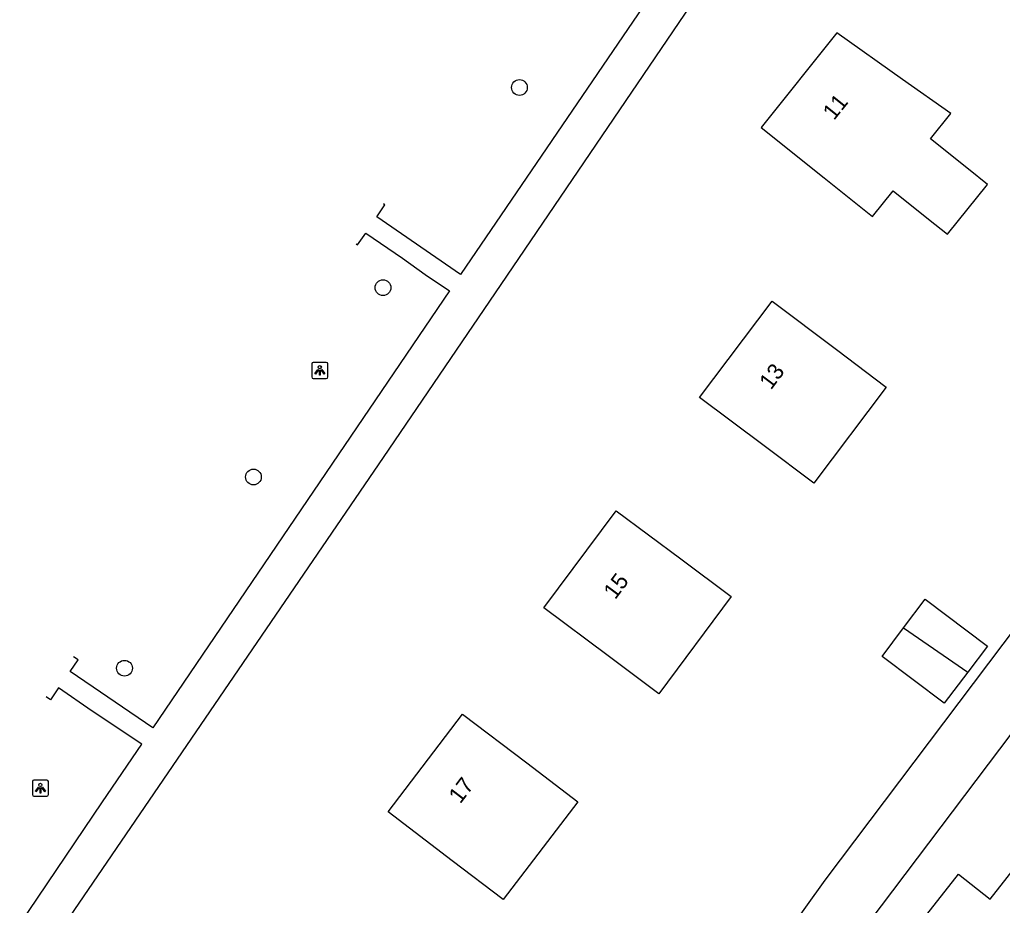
# Model space of a CAD drawing. Extents: x 158797 to 159887, y 384318 to 385255.
# Drawn here: x 159089 to 159149.9, y 385000.3 to 385055.3 of the extents above; entities that cross this region are included whole.
import ezdxf

# ---------------------------------------------------------------- set-up
doc = ezdxf.new("R2010")
doc.units = 0
for name, color, linetype in [('IMGEO_Boom', 7, 'Continuous'), ('IMGEO_Lichtpunt', 7, 'Continuous'), ('IMGEO_Pand', 7, 'Continuous'), ('IMGEO_Pand_nummerreeks', 7, 'Continuous'), ('IMGEO_Parkeervlak_open', 7, 'Continuous'), ('IMGEO_Rijbaan_lokaal_open', 7, 'Continuous'), ('IMGEO_Voetpad_open', 7, 'Continuous')]:
    doc.layers.add(name, color=color, linetype=linetype)

msp = doc.modelspace()

# ---------------------------------------------------------------- linework, layer by layer
at = {"layer": 'IMGEO_Boom'}
for centre in [(159119.974, 385051.109), (159111.509, 385038.687), (159103.468, 385026.934), (159095.468, 385015.062)]:
    msp.add_circle(centre, 0.489, dxfattribs=at)
at = {"layer": 'IMGEO_Lichtpunt'}
for p, q in [((159107.087, 385033.95), (159107.087, 385033.143)), ((159107.087, 385033.95), (159107.087, 385033.143)), ((159107.989, 385034.045), (159107.181, 385034.045)), ((159107.989, 385034.045), (159107.181, 385034.045)), ((159108.083, 385033.143), (159108.083, 385033.95)), ((159108.083, 385033.143), (159108.083, 385033.95)), ((159107.181, 385033.049), (159107.989, 385033.049)), ((159107.181, 385033.049), (159107.989, 385033.049)), ((159089.75, 385008.021), (159089.75, 385007.214)), ((159089.75, 385008.021), (159089.75, 385007.214)), ((159090.652, 385008.116), (159089.844, 385008.116)), ((159090.652, 385008.116), (159089.844, 385008.116)), ((159090.746, 385007.214), (159090.746, 385008.021)), ((159090.746, 385007.214), (159090.746, 385008.021)), ((159089.844, 385007.12), (159090.652, 385007.12)), ((159089.844, 385007.12), (159090.652, 385007.12))]:
    msp.add_line(p, q, dxfattribs=at)
for points in [[(159107.461, 385033.614), (159107.5, 385033.586), (159107.312, 385033.324), (159107.274, 385033.351), (159107.461, 385033.614)], [(159107.673, 385033.586), (159107.711, 385033.613), (159107.898, 385033.351), (159107.859, 385033.323), (159107.673, 385033.586)], [(159107.563, 385033.566), (159107.61, 385033.566), (159107.61, 385033.244), (159107.563, 385033.244), (159107.563, 385033.566)], [(159090.124, 385007.685), (159090.163, 385007.657), (159089.975, 385007.395), (159089.937, 385007.422), (159090.124, 385007.685)], [(159090.226, 385007.637), (159090.273, 385007.637), (159090.273, 385007.315), (159090.226, 385007.315), (159090.226, 385007.637)], [(159090.336, 385007.657), (159090.374, 385007.684), (159090.561, 385007.422), (159090.522, 385007.394), (159090.336, 385007.657)]]:
    msp.add_lwpolyline(points, dxfattribs=at)
for centre in [(159107.586, 385033.748), (159090.249, 385007.819)]:
    msp.add_circle(centre, 0.0994, dxfattribs=at)
for centre, start, end in [((159107.181, 385033.95), 90, 180), ((159107.181, 385033.95), 90, 180), ((159107.989, 385033.95), 0, 90), ((159107.989, 385033.95), 0, 90), ((159107.181, 385033.143), 180, 270), ((159107.181, 385033.143), 180, 270), ((159107.989, 385033.143), 270, 0), ((159107.989, 385033.143), 270, 360), ((159089.844, 385008.021), 90, 180), ((159089.844, 385008.021), 90, 180), ((159090.652, 385008.021), 0, 90), ((159090.652, 385008.021), 0, 90), ((159089.844, 385007.214), 180, 270), ((159089.844, 385007.214), 180, 270), ((159090.652, 385007.214), 270, 0), ((159090.652, 385007.214), 270, 360)]:
    msp.add_arc(centre, 0.0946, start, end, dxfattribs=at)
at = {"layer": 'IMGEO_Pand'}
for points in [[(159146.742, 385049.501), (159143.755, 385051.61), (159139.67, 385054.493), (159134.977, 385048.636), (159138.879, 385045.509), (159141.893, 385043.095), (159143.175, 385044.694), (159145.367, 385042.938), (159146.541, 385041.998), (159149.023, 385045.095), (159147.849, 385046.035), (159145.484, 385047.93), (159146.742, 385049.501)], [(159138.24, 385026.54), (159135.153, 385028.862), (159131.156, 385031.867), (159135.648, 385037.841), (159139.645, 385034.836), (159142.732, 385032.514), (159138.24, 385026.54)], [(159133.12, 385019.506), (159128.621, 385013.483), (159125.487, 385015.825), (159121.481, 385018.817), (159125.98, 385024.84), (159129.986, 385021.848), (159133.12, 385019.506)], [(159143.81, 385017.566), (159145.153, 385019.345), (159149.016, 385016.43), (159147.801, 385014.82)], [(159147.801, 385014.82), (159146.34, 385012.885), (159142.478, 385015.8), (159143.81, 385017.566)], [(159143.81, 385017.566), (159147.801, 385014.82)], [(159120.428, 385009.181), (159123.592, 385006.771), (159118.969, 385000.701), (159115.805, 385003.111), (159111.828, 385006.141), (159116.451, 385012.211), (159120.428, 385009.181)]]:
    msp.add_lwpolyline(points, dxfattribs=at)
at = {"layer": 'IMGEO_Parkeervlak_open'}
msp.add_lwpolyline([(159134.343, 384989.569), (159137.859, 384990.346), (159147.215, 385002.279), (159149.19, 385000.73), (159177.289, 385036.566), (159175.37, 385038.106)], dxfattribs=at)
at = {"layer": 'IMGEO_Rijbaan_lokaal_open'}
for points in [[(159134.343, 384989.569), (159172.636, 385040.299)], [(159155.296, 385029.857), (159158.018, 385027.678), (159150.926, 385017.823), (159138.932, 385001.917), (159132.728, 384993.243), (159130.621, 384989.574), (159130.802, 384982.659), (159131.968, 384977.645), (159135.618, 384964.166), (159143.646, 384954.591)]]:
    msp.add_lwpolyline(points, dxfattribs=at)
at = {"layer": 'IMGEO_Voetpad_open'}
for points in [[(159127.349, 384969.38), (159127.169, 384969.189), (159124.279, 384971.818), (159124.18, 384971.909), (159120.786, 384975), (159118.4, 384977.13), (159117.408, 384976.04), (159110.076, 384982.302), (159103.204, 384987.734), (159092.362, 384995.835), (159091.494, 384998.786), (159111.535, 385028.137), (159118.837, 385038.88), (159135.41, 385063.302), (159135.306, 385063.376), (159146.569, 385079.985), (159151.5, 385087.223)], [(159128.083, 385068.051), (159133.316, 385064.48), (159116.322, 385039.492), (159111.128, 385043.073), (159111.615, 385043.835), (159111.544, 385043.883)], [(159109.844, 385041.399), (159109.934, 385041.339), (159110.446, 385042.074), (159112.719, 385040.516), (159114.127, 385039.508), (159115.644, 385038.496), (159097.226, 385011.36), (159092.088, 385014.853), (159092.584, 385015.582), (159092.304, 385015.767)], [(159089.625, 384996.759), (159088.962, 384999.139), (159094.107, 385006.771), (159096.534, 385010.341), (159093.469, 385012.397), (159091.377, 385013.835), (159090.881, 385013.109), (159090.611, 385013.292)]]:
    msp.add_lwpolyline(points, dxfattribs=at)

# ---------------------------------------------------------------- texts
at = {"layer": 'IMGEO_Pand_nummerreeks'}
for s, rotation, p in [('11', 51.29691, (159139.495, 385049.029)), ('13', 53.05958, (159135.582, 385032.295)), ('15', 53.24138, (159125.918, 385019.277)), ('17', 52.70658, (159116.304, 385006.604))]:
    msp.add_text(s, height=1, rotation=rotation, dxfattribs=at).set_placement(p)

doc.saveas('drawing.dxf')
